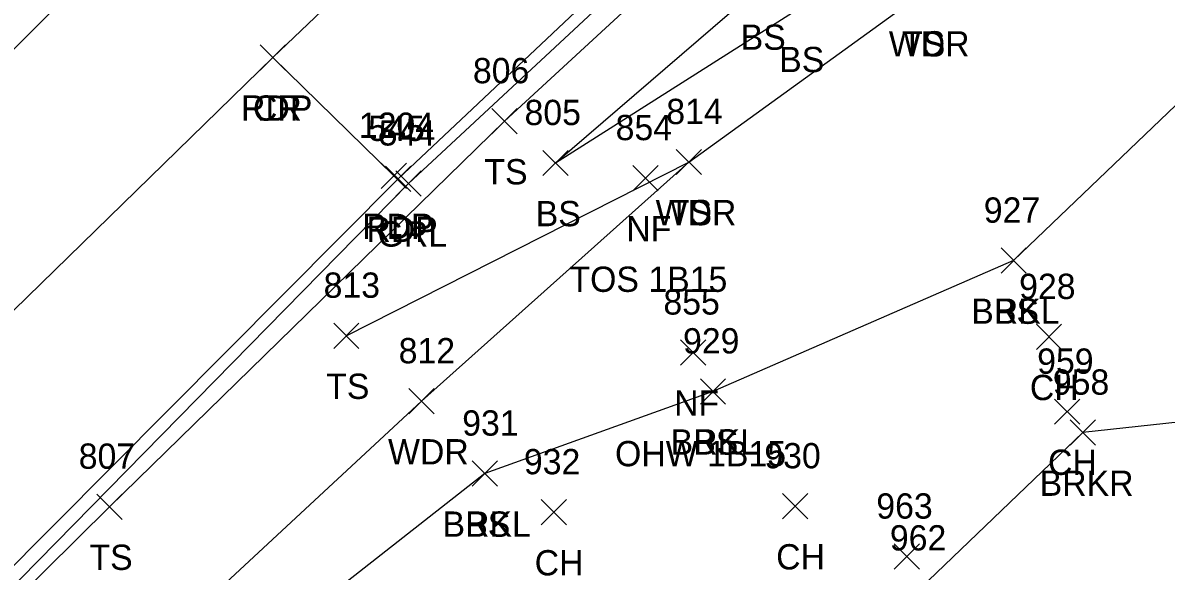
# Model space of a CAD drawing. Extents: x 1528286 to 1556263, y 492387 to 508952.
# Drawn here: x 1528382.4 to 1528472.8, y 492537.5 to 492580.9 of the extents above; entities that cross this region are included whole.
import ezdxf

# ---------------------------------------------------------------- set-up
doc = ezdxf.new("R2010")
doc.units = 0
for name, color, linetype in [('L_A', 7, 'Continuous'), ('L_C', 7, 'Continuous'), ('L_I', 7, 'Continuous'), ('L_TIC', 7, 'Continuous'), ('LAWA', 7, 'Continuous'), ('LAWE', 7, 'Continuous'), ('LELB', 7, 'Continuous'), ('P_A', 7, 'Continuous'), ('P_I', 7, 'Continuous'), ('P_TIC', 7, 'Continuous'), ('PET', 7, 'Continuous'), ('PRC', 7, 'Continuous'), ('R_A', 7, 'Continuous'), ('R_I', 7, 'Continuous'), ('R_TIC', 7, 'Continuous'), ('RGR', 7, 'Continuous')]:
    doc.layers.add(name, color=color, linetype=linetype)

msp = doc.modelspace()

# ---------------------------------------------------------------- linework, layer by layer
at = {"layer": 'L_TIC'}
for points in [[(1528419.499, 492572.078), (1528421.499, 492574.078)], [(1528421.499, 492572.078), (1528419.499, 492574.078)], [(1528419.499, 492572.078), (1528421.499, 492574.078)], [(1528421.499, 492572.078), (1528419.499, 492574.078)], [(1528423.526, 492568.769), (1528425.526, 492570.769)], [(1528425.526, 492568.769), (1528423.526, 492570.769)], [(1528423.526, 492568.769), (1528425.526, 492570.769)], [(1528425.526, 492568.769), (1528423.526, 492570.769)], [(1528423.526, 492568.769), (1528425.526, 492570.769)], [(1528425.526, 492568.769), (1528423.526, 492570.769)], [(1528423.526, 492568.769), (1528425.526, 492570.769)], [(1528425.526, 492568.769), (1528423.526, 492570.769)], [(1528434.091, 492568.848), (1528436.091, 492570.848)], [(1528436.091, 492568.848), (1528434.091, 492570.848)], [(1528434.091, 492568.848), (1528436.091, 492570.848)], [(1528436.091, 492568.848), (1528434.091, 492570.848)], [(1528434.091, 492568.848), (1528436.091, 492570.848)], [(1528436.091, 492568.848), (1528434.091, 492570.848)], [(1528434.091, 492568.848), (1528436.091, 492570.848)], [(1528436.091, 492568.848), (1528434.091, 492570.848)], [(1528430.654, 492567.576), (1528432.654, 492569.576)], [(1528432.654, 492567.576), (1528430.654, 492569.576)], [(1528430.654, 492567.576), (1528432.654, 492569.576)], [(1528432.654, 492567.576), (1528430.654, 492569.576)], [(1528459.774, 492561.048), (1528461.774, 492563.048)], [(1528461.774, 492561.048), (1528459.774, 492563.048)], [(1528459.774, 492561.048), (1528461.774, 492563.048)], [(1528461.774, 492561.048), (1528459.774, 492563.048)], [(1528459.774, 492561.048), (1528461.774, 492563.048)], [(1528461.774, 492561.048), (1528459.774, 492563.048)], [(1528459.774, 492561.048), (1528461.774, 492563.048)], [(1528461.774, 492561.048), (1528459.774, 492563.048)], [(1528406.988, 492555.109), (1528408.988, 492557.109)], [(1528408.988, 492555.109), (1528406.988, 492557.109)], [(1528406.988, 492555.109), (1528408.988, 492557.109)], [(1528408.988, 492555.109), (1528406.988, 492557.109)], [(1528462.569, 492555.014), (1528464.569, 492557.014)], [(1528464.569, 492555.014), (1528462.569, 492557.014)], [(1528462.569, 492555.014), (1528464.569, 492557.014)], [(1528464.569, 492555.014), (1528462.569, 492557.014)], [(1528434.432, 492553.78), (1528436.432, 492555.78)], [(1528436.432, 492553.78), (1528434.432, 492555.78)], [(1528434.432, 492553.78), (1528436.432, 492555.78)], [(1528436.432, 492553.78), (1528434.432, 492555.78)], [(1528435.992, 492550.704), (1528437.992, 492552.704)], [(1528437.992, 492550.704), (1528435.992, 492552.704)], [(1528435.992, 492550.704), (1528437.992, 492552.704)], [(1528437.992, 492550.704), (1528435.992, 492552.704)], [(1528435.992, 492550.704), (1528437.992, 492552.704)], [(1528437.992, 492550.704), (1528435.992, 492552.704)], [(1528435.992, 492550.704), (1528437.992, 492552.704)], [(1528437.992, 492550.704), (1528435.992, 492552.704)], [(1528412.925, 492549.925), (1528414.925, 492551.925)], [(1528414.925, 492549.925), (1528412.925, 492551.925)], [(1528412.925, 492549.925), (1528414.925, 492551.925)], [(1528414.925, 492549.925), (1528412.925, 492551.925)], [(1528464.004, 492549.099), (1528466.004, 492551.099)], [(1528466.004, 492549.099), (1528464.004, 492551.099)], [(1528464.004, 492549.099), (1528466.004, 492551.099)], [(1528466.004, 492549.099), (1528464.004, 492551.099)], [(1528465.236, 492547.442), (1528467.236, 492549.442)], [(1528467.236, 492547.442), (1528465.236, 492549.442)], [(1528465.236, 492547.442), (1528467.236, 492549.442)], [(1528467.236, 492547.442), (1528465.236, 492549.442)], [(1528417.951, 492544.204), (1528419.951, 492546.204)], [(1528419.951, 492544.204), (1528417.951, 492546.204)], [(1528417.951, 492544.204), (1528419.951, 492546.204)], [(1528419.951, 492544.204), (1528417.951, 492546.204)], [(1528417.951, 492544.204), (1528419.951, 492546.204)], [(1528419.951, 492544.204), (1528417.951, 492546.204)], [(1528417.951, 492544.204), (1528419.951, 492546.204)], [(1528419.951, 492544.204), (1528417.951, 492546.204)], [(1528388.262, 492541.582), (1528390.262, 492543.582)], [(1528390.262, 492541.582), (1528388.262, 492543.582)], [(1528388.262, 492541.582), (1528390.262, 492543.582)], [(1528390.262, 492541.582), (1528388.262, 492543.582)], [(1528423.398, 492541.148), (1528425.398, 492543.148)], [(1528425.398, 492541.148), (1528423.398, 492543.148)], [(1528423.398, 492541.148), (1528425.398, 492543.148)], [(1528425.398, 492541.148), (1528423.398, 492543.148)], [(1528442.5, 492541.619), (1528444.5, 492543.619)], [(1528444.5, 492541.619), (1528442.5, 492543.619)], [(1528442.5, 492541.619), (1528444.5, 492543.619)], [(1528444.5, 492541.619), (1528442.5, 492543.619)], [(1528451.318, 492537.639), (1528453.318, 492539.639)], [(1528453.318, 492537.639), (1528451.318, 492539.639)], [(1528451.318, 492537.639), (1528453.318, 492539.639)], [(1528453.318, 492537.639), (1528451.318, 492539.639)]]:
    msp.add_lwpolyline(points, dxfattribs=at)
at = {"layer": 'LAWA'}
msp.add_lwpolyline([(1528350.567, 492486.658), (1528374.131, 492513.994), (1528413.925, 492550.925), (1528435.091, 492569.848), (1528453.537, 492583.197), (1528487.048, 492613.162), (1528503.178, 492626.813), (1528522.579, 492648.478), (1528559.072, 492677.555), (1528579.271, 492695.125), (1528598.445, 492712.961), (1528609.007, 492715.026)], dxfattribs=at)
msp.add_lwpolyline([(1528350.567, 492486.658), (1528374.131, 492513.994), (1528413.925, 492550.925), (1528435.091, 492569.848), (1528453.537, 492583.197), (1528487.048, 492613.162), (1528503.178, 492626.813), (1528522.579, 492648.478), (1528559.072, 492677.555), (1528579.271, 492695.125), (1528598.445, 492712.961), (1528609.007, 492715.026)], dxfattribs=at)
at = {"layer": 'LAWE'}
for points in [[(1528639.893, 492735.148), (1528628.638, 492716.197), (1528619.322, 492697.772), (1528600.014, 492685.78), (1528586.494, 492675.208), (1528555.765, 492651.711), (1528552.059, 492644.142), (1528537.626, 492632.534), (1528523.345, 492621.851), (1528510.87, 492609.533), (1528497.291, 492599.489), (1528482.777, 492583.151), (1528460.774, 492562.048), (1528436.992, 492551.704), (1528418.951, 492545.204), (1528399.482, 492529.93), (1528387.952, 492519.312), (1528358.196, 492480.955)], [(1528639.893, 492735.148), (1528628.638, 492716.197), (1528619.322, 492697.772), (1528600.014, 492685.78), (1528586.494, 492675.208), (1528555.765, 492651.711), (1528552.059, 492644.142), (1528537.626, 492632.534), (1528523.345, 492621.851), (1528510.87, 492609.533), (1528497.291, 492599.489), (1528482.777, 492583.151), (1528460.774, 492562.048), (1528436.992, 492551.704), (1528418.951, 492545.204), (1528399.482, 492529.93), (1528387.952, 492519.312), (1528358.196, 492480.955)], [(1528645.438, 492730.638), (1528651.622, 492718.642), (1528645.743, 492704.772), (1528631.806, 492684.8), (1528615.475, 492671.091), (1528597.131, 492648.324), (1528570.323, 492633.929), (1528549.926, 492614.136), (1528527.115, 492580.823), (1528486.911, 492550.694), (1528466.236, 492548.442), (1528453.392, 492536.119), (1528428.919, 492520.065), (1528405.493, 492507.44), (1528391.912, 492487.091), (1528384.545, 492464.65)], [(1528645.438, 492730.638), (1528651.622, 492718.642), (1528645.743, 492704.772), (1528631.806, 492684.8), (1528615.475, 492671.091), (1528597.131, 492648.324), (1528570.323, 492633.929), (1528549.926, 492614.136), (1528527.115, 492580.823), (1528486.911, 492550.694), (1528466.236, 492548.442), (1528453.392, 492536.119), (1528428.919, 492520.065), (1528405.493, 492507.44), (1528391.912, 492487.091), (1528384.545, 492464.65)]]:
    msp.add_lwpolyline(points, dxfattribs=at)
at = {"layer": 'LELB'}
for points in [[(1528627.535, 492747.197), (1528602.245, 492728.24), (1528590.919, 492720.18), (1528561.7, 492697.236), (1528528.44, 492669.894), (1528504.886, 492649.176), (1528486.55, 492633.133), (1528477.153, 492624.603), (1528462.188, 492611.303), (1528435.473, 492586.893), (1528420.499, 492573.078), (1528389.262, 492542.582), (1528363.671, 492517.292), (1528340.83, 492494.601)], [(1528627.535, 492747.197), (1528602.245, 492728.24), (1528590.919, 492720.18), (1528561.7, 492697.236), (1528528.44, 492669.894), (1528504.886, 492649.176), (1528486.55, 492633.133), (1528477.153, 492624.603), (1528462.188, 492611.303), (1528435.473, 492586.893), (1528420.499, 492573.078), (1528389.262, 492542.582), (1528363.671, 492517.292), (1528340.83, 492494.601)], [(1528619.629, 492709.303), (1528607.886, 492695.261), (1528600.014, 492685.78), (1528586.494, 492675.208), (1528555.765, 492651.711), (1528552.059, 492644.142), (1528537.626, 492632.534), (1528523.345, 492621.851), (1528510.87, 492609.533), (1528497.291, 492599.489), (1528482.777, 492583.151), (1528460.774, 492562.048), (1528436.992, 492551.704), (1528418.951, 492545.204), (1528399.482, 492529.93), (1528387.952, 492519.312), (1528358.196, 492480.955)], [(1528619.629, 492709.303), (1528607.886, 492695.261), (1528600.014, 492685.78), (1528586.494, 492675.208), (1528555.765, 492651.711), (1528552.059, 492644.142), (1528537.626, 492632.534), (1528523.345, 492621.851), (1528510.87, 492609.533), (1528497.291, 492599.489), (1528482.777, 492583.151), (1528460.774, 492562.048), (1528436.992, 492551.704), (1528418.951, 492545.204), (1528399.482, 492529.93), (1528387.952, 492519.312), (1528358.196, 492480.955)], [(1528487.933, 492626.516), (1528480.875, 492624.184), (1528464.603, 492607.884), (1528440.739, 492583.726), (1528424.526, 492569.769)], [(1528487.933, 492626.516), (1528480.875, 492624.184), (1528464.603, 492607.884), (1528440.739, 492583.726), (1528424.526, 492569.769)], [(1528489.009, 492622.822), (1528480.293, 492619.802), (1528467.677, 492606.034), (1528443.787, 492581.956), (1528424.526, 492569.769)], [(1528489.009, 492622.822), (1528480.293, 492619.802), (1528467.677, 492606.034), (1528443.787, 492581.956), (1528424.526, 492569.769)], [(1528407.988, 492556.109), (1528435.091, 492569.848), (1528453.537, 492583.197), (1528487.048, 492613.162), (1528483.53, 492620.801)], [(1528407.988, 492556.109), (1528435.091, 492569.848), (1528453.537, 492583.197), (1528487.048, 492613.162), (1528483.53, 492620.801)]]:
    msp.add_lwpolyline(points, dxfattribs=at)
at = {"layer": 'P_TIC'}
for points in [[(1528401.171, 492577.118), (1528403.171, 492579.118)], [(1528403.171, 492577.118), (1528401.171, 492579.118)], [(1528401.171, 492577.118), (1528403.171, 492579.118)], [(1528403.171, 492577.118), (1528401.171, 492579.118)], [(1528401.171, 492577.118), (1528403.171, 492579.118)], [(1528403.171, 492577.118), (1528401.171, 492579.118)], [(1528401.171, 492577.118), (1528403.171, 492579.118)], [(1528403.171, 492577.118), (1528401.171, 492579.118)], [(1528410.75, 492567.76), (1528412.75, 492569.76)], [(1528412.75, 492567.76), (1528410.75, 492569.76)], [(1528410.75, 492567.76), (1528412.75, 492569.76)], [(1528412.75, 492567.76), (1528410.75, 492569.76)], [(1528411.089, 492567.516), (1528413.089, 492569.516)], [(1528413.089, 492567.516), (1528411.089, 492569.516)], [(1528411.089, 492567.516), (1528413.089, 492569.516)], [(1528413.089, 492567.516), (1528411.089, 492569.516)]]:
    msp.add_lwpolyline(points, dxfattribs=at)
at = {"layer": 'PET'}
for points in [[(1528560.517, 492699.264), (1528557.469, 492699.118), (1528553.458, 492694.773), (1528549.097, 492692.715), (1528547.05, 492688.292), (1528537.757, 492682.515), (1528535.94, 492680.254), (1528535.911, 492679.061), (1528519.42, 492665.123), (1528485.647, 492635.106), (1528449.898, 492603.317), (1528443.292, 492597.221), (1528441.443, 492597.056), (1528433.939, 492590.577), (1528430.616, 492585.987), (1528412.089, 492568.516), (1528375.77, 492531.986), (1528339.078, 492496.271)], [(1528560.517, 492699.264), (1528557.469, 492699.118), (1528553.458, 492694.773), (1528549.097, 492692.715), (1528547.05, 492688.292), (1528537.757, 492682.515), (1528535.94, 492680.254), (1528535.911, 492679.061), (1528519.42, 492665.123), (1528485.647, 492635.106), (1528449.898, 492603.317), (1528443.292, 492597.221), (1528441.443, 492597.056), (1528433.939, 492590.577), (1528430.616, 492585.987), (1528412.089, 492568.516), (1528375.77, 492531.986), (1528339.078, 492496.271)], [(1528466.456, 492657.166), (1528429.377, 492624.126), (1528391.881, 492588.941), (1528355.416, 492552.695), (1528318.996, 492516.325)], [(1528466.456, 492657.166), (1528429.377, 492624.126), (1528391.881, 492588.941), (1528355.416, 492552.695), (1528318.996, 492516.325)], [(1528336.327, 492494.34), (1528327.092, 492503.996), (1528363.319, 492540.232), (1528402.171, 492578.118), (1528411.75, 492568.76)], [(1528336.327, 492494.34), (1528327.092, 492503.996), (1528363.319, 492540.232), (1528402.171, 492578.118), (1528411.75, 492568.76)], [(1528411.75, 492568.76), (1528412.089, 492568.516)], [(1528411.75, 492568.76), (1528412.089, 492568.516)]]:
    msp.add_lwpolyline(points, dxfattribs=at)
at = {"layer": 'PRC'}
for points in [[(1528402.171, 492578.118), (1528439.483, 492613.677)], [(1528402.171, 492578.118), (1528439.483, 492613.677)], [(1528327.092, 492503.996), (1528363.319, 492540.232), (1528402.171, 492578.118)], [(1528327.092, 492503.996), (1528363.319, 492540.232), (1528402.171, 492578.118)]]:
    msp.add_lwpolyline(points, dxfattribs=at)
at = {"layer": 'R_TIC'}
for points in [[(1528411.918, 492567.153), (1528413.918, 492569.153)], [(1528413.918, 492567.153), (1528411.918, 492569.153)], [(1528411.918, 492567.153), (1528413.918, 492569.153)], [(1528413.918, 492567.153), (1528411.918, 492569.153)]]:
    msp.add_lwpolyline(points, dxfattribs=at)
at = {"layer": 'RGR'}
msp.add_lwpolyline([(1528631.557, 492751.518), (1528593.228, 492723.7), (1528555.254, 492694.171), (1528520.288, 492664.562), (1528486.051, 492634.677), (1528450.283, 492602.919), (1528412.918, 492568.153), (1528376.626, 492531.198), (1528339.769, 492495.46)], dxfattribs=at)
msp.add_lwpolyline([(1528631.557, 492751.518), (1528593.228, 492723.7), (1528555.254, 492694.171), (1528520.288, 492664.562), (1528486.051, 492634.677), (1528450.283, 492602.919), (1528412.918, 492568.153), (1528376.626, 492531.198), (1528339.769, 492495.46)], dxfattribs=at)

# ---------------------------------------------------------------- texts
at = {"layer": 'L_A'}
for s, p in [('BS', (1528439.18, 492578.726)), ('BS', (1528439.18, 492578.726)), ('WDR', (1528450.899, 492578.197)), ('WDR', (1528450.899, 492578.197)), ('TS', (1528451.946, 492578.197)), ('TS', (1528451.946, 492578.197)), ('BS', (1528442.228, 492576.956)), ('BS', (1528442.228, 492576.956)), ('TS', (1528418.909, 492568.078)), ('TS', (1528418.909, 492568.078)), ('BS', (1528422.967, 492564.769)), ('BS', (1528422.967, 492564.769)), ('BS', (1528422.967, 492564.769)), ('BS', (1528422.967, 492564.769)), ('WDR', (1528432.454, 492564.848)), ('WDR', (1528432.454, 492564.848)), ('TS', (1528433.501, 492564.848)), ('TS', (1528433.501, 492564.848)), ('NF', (1528430.134, 492563.576)), ('NF', (1528430.134, 492563.576)), ('BRKL', (1528457.419, 492557.048)), ('BRKL', (1528457.419, 492557.048)), ('BS', (1528459.215, 492557.048)), ('BS', (1528459.215, 492557.048)), ('TS', (1528406.398, 492551.109)), ('TS', (1528406.398, 492551.109)), ('CH', (1528462.057, 492551.014)), ('CH', (1528462.057, 492551.014)), ('NF', (1528433.913, 492549.78)), ('NF', (1528433.913, 492549.78)), ('BRKL', (1528433.637, 492546.704)), ('BRKL', (1528433.637, 492546.704)), ('BS', (1528435.433, 492546.704)), ('BS', (1528435.433, 492546.704)), ('WDR', (1528411.287, 492545.925)), ('WDR', (1528411.287, 492545.925)), ('CH', (1528463.492, 492545.099)), ('CH', (1528463.492, 492545.099)), ('BRKR', (1528462.827, 492543.442)), ('BRKR', (1528462.827, 492543.442)), ('BRKL', (1528415.597, 492540.204)), ('BRKL', (1528415.597, 492540.204)), ('BS', (1528417.392, 492540.204)), ('BS', (1528417.392, 492540.204)), ('TS', (1528387.671, 492537.582)), ('TS', (1528387.671, 492537.582)), ('CH', (1528441.988, 492537.619)), ('CH', (1528441.988, 492537.619)), ('CH', (1528422.886, 492537.148)), ('CH', (1528422.886, 492537.148))]:
    msp.add_text(s, height=2, dxfattribs=at).set_placement(p)
at = {"layer": 'L_C'}
for s, p in [('TOS 1B15', (1528425.638, 492559.576)), ('TOS 1B15', (1528425.638, 492559.576)), ('OHW 1B15', (1528429.243, 492545.78)), ('OHW 1B15', (1528429.243, 492545.78))]:
    msp.add_text(s, height=2, dxfattribs=at).set_placement(p)
at = {"layer": 'L_I'}
for s, p in [('806', (1528418.003, 492576.078)), ('806', (1528418.003, 492576.078)), ('805', (1528422.085, 492572.769)), ('805', (1528422.085, 492572.769)), ('805', (1528422.085, 492572.769)), ('805', (1528422.085, 492572.769)), ('814', (1528433.296, 492572.848)), ('814', (1528433.296, 492572.848)), ('814', (1528433.296, 492572.848)), ('814', (1528433.296, 492572.848)), ('854', (1528429.291, 492571.576)), ('854', (1528429.291, 492571.576)), ('927', (1528458.412, 492565.048)), ('927', (1528458.412, 492565.048)), ('927', (1528458.412, 492565.048)), ('927', (1528458.412, 492565.048)), ('813', (1528406.193, 492559.109)), ('813', (1528406.193, 492559.109)), ('928', (1528461.207, 492559.014)), ('928', (1528461.207, 492559.014)), ('855', (1528433.07, 492557.78)), ('855', (1528433.07, 492557.78)), ('929', (1528434.622, 492554.704)), ('929', (1528434.622, 492554.704)), ('929', (1528434.622, 492554.704)), ('929', (1528434.622, 492554.704)), ('812', (1528412.13, 492553.925)), ('812', (1528412.13, 492553.925)), ('959', (1528462.634, 492553.099)), ('959', (1528462.634, 492553.099)), ('958', (1528463.874, 492551.442)), ('958', (1528463.874, 492551.442)), ('931', (1528417.156, 492548.204)), ('931', (1528417.156, 492548.204)), ('931', (1528417.156, 492548.204)), ('931', (1528417.156, 492548.204)), ('807', (1528386.821, 492545.582)), ('807', (1528386.821, 492545.582)), ('930', (1528441.051, 492545.619)), ('930', (1528441.051, 492545.619)), ('932', (1528422.036, 492545.148)), ('932', (1528422.036, 492545.148)), ('963', (1528449.909, 492541.639)), ('963', (1528449.909, 492541.639)), ('962', (1528450.983, 492539.119)), ('962', (1528450.983, 492539.119))]:
    msp.add_text(s, height=2, dxfattribs=at).set_placement(p)
at = {"layer": 'P_A'}
for s, p in [('RDP', (1528399.659, 492573.118)), ('RDP', (1528399.659, 492573.118)), ('CR', (1528400.604, 492573.118)), ('CR', (1528400.604, 492573.118)), ('RDP', (1528409.238, 492563.76)), ('RDP', (1528409.238, 492563.76)), ('RDP', (1528409.577, 492563.516)), ('RDP', (1528409.577, 492563.516))]:
    msp.add_text(s, height=2, dxfattribs=at).set_placement(p)
at = {"layer": 'P_I'}
for s, p in [('1204', (1528408.978, 492571.76)), ('1204', (1528408.978, 492571.76)), ('545', (1528409.726, 492571.516)), ('545', (1528409.726, 492571.516))]:
    msp.add_text(s, height=2, dxfattribs=at).set_placement(p)
at = {"layer": 'R_A'}
msp.add_text('GRL', height=2, dxfattribs=at).set_placement((1528410.461, 492563.153))
msp.add_text('GRL', height=2, dxfattribs=at).set_placement((1528410.461, 492563.153))
at = {"layer": 'R_I'}
msp.add_text('544', height=2, dxfattribs=at).set_placement((1528410.556, 492571.153))
msp.add_text('544', height=2, dxfattribs=at).set_placement((1528410.556, 492571.153))

doc.saveas('drawing.dxf')
